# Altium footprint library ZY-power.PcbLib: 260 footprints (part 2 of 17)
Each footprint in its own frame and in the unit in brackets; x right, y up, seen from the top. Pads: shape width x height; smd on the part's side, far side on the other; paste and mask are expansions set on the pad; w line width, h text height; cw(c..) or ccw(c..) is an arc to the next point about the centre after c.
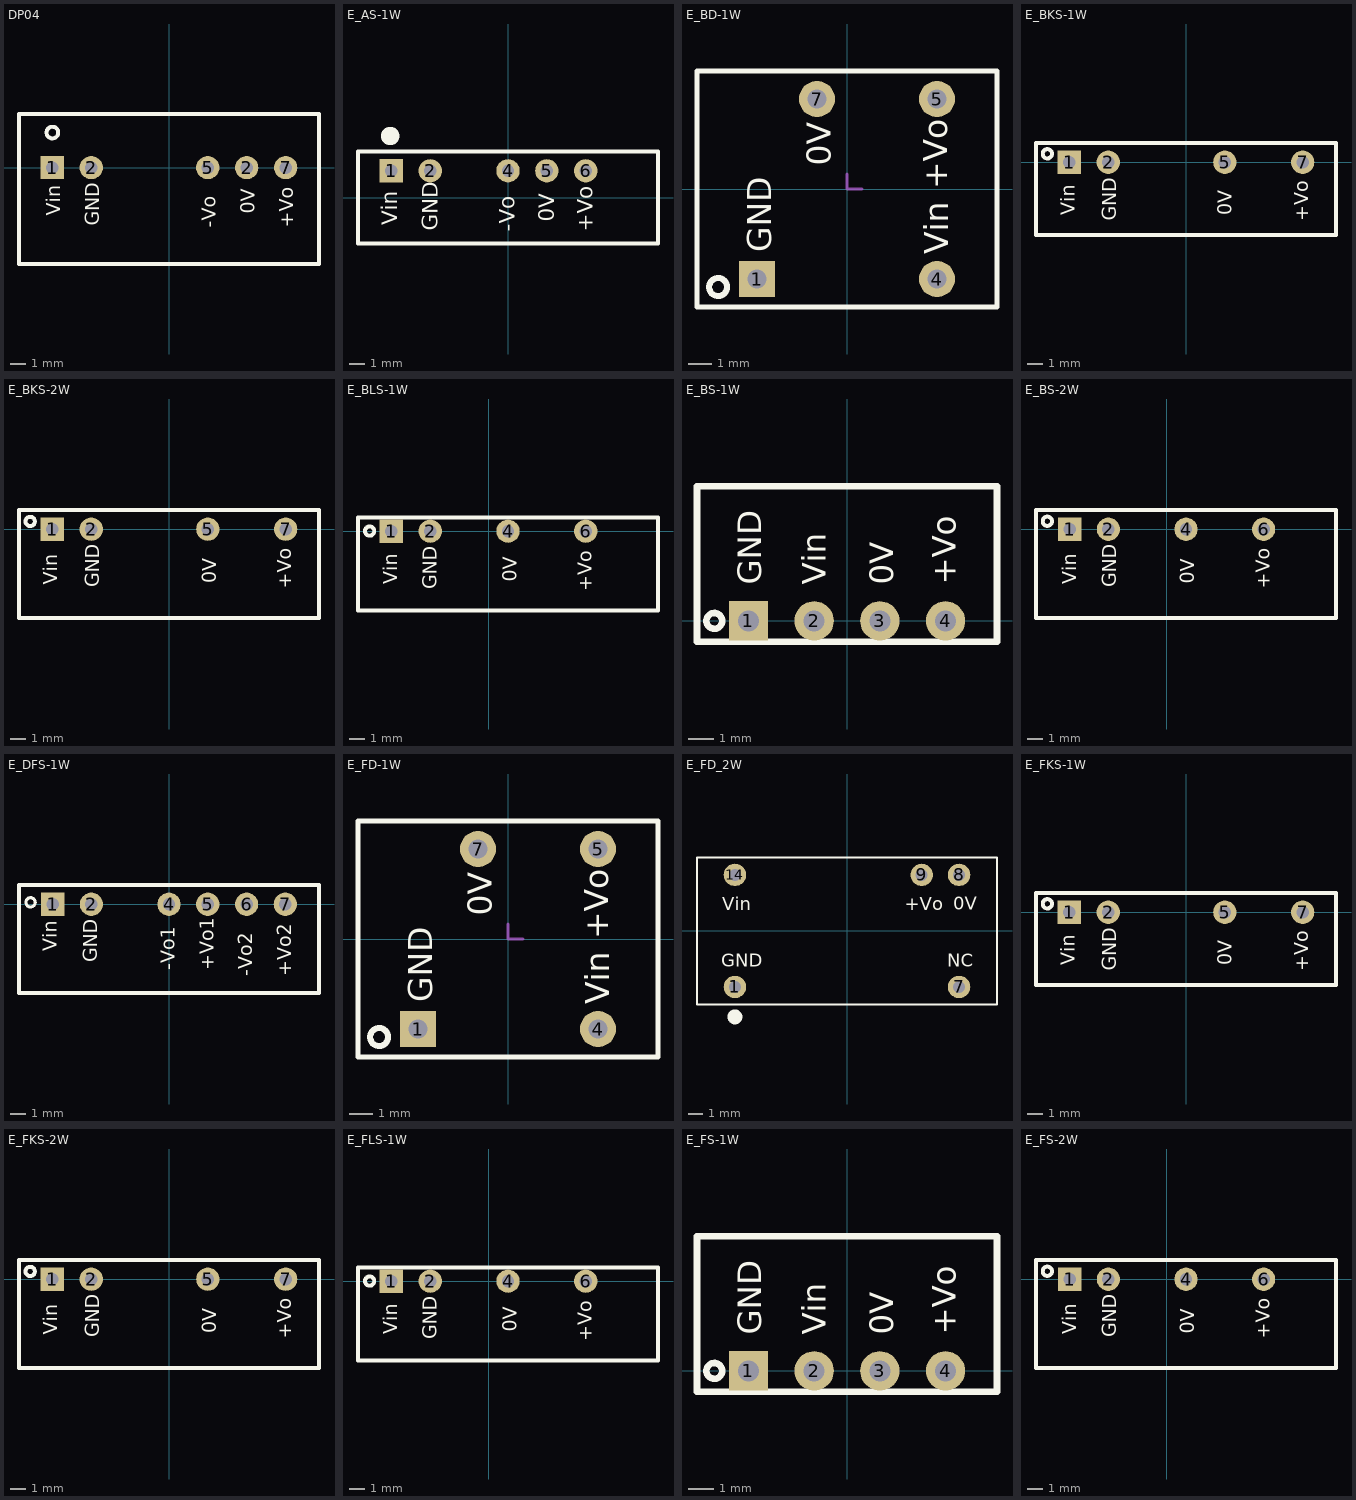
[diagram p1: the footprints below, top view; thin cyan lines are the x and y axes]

## DP04 [mil]
height 492.13
pads (5):
  rect 60x60 hole 32: 1(-300,0)
  round 60 hole 32: 2(-200,0) 2(199.74,0) 5(99.74,0) 7(300,0)
Top Overlay:
  circle w10: c-300,90 r15
  lines w10: -385.83,-248.03 -385.83,137.8 385.83,137.8 385.83,-248.03 -385.83,-248.03
  text "Vin" at -280,-123.29 h36
  text "GND" at -180,-150 h36
  text "-Vo" at 120,-155 h36
  text "+Vo" at 320,-155 h36
  text "0V" at 220,-118.67 h36

## E_AS-1W [mil]
height 393.7
pads (5):
  rect 60x60 hole 32: 1(-300,68.9)
  round 60 hole 32: 2(-200,68.9) 4(0,68.9) 5(100,68.9) 6(200,68.9)
Top Overlay:
  circle w39.37: c-303.15,158.46 r3.94
  lines w10: -385.83,-118.11 -385.83,118.11 385.83,118.11 385.83,-118.11 -385.83,-118.11
  text "Vin" at -284.45,-70.87 h40
  text "GND" at -180.12,-84.65 h40
  text "-Vo" at 17.72,-87.6 h40
  text "0V" at 118.6,-61.99 h40
  text "+Vo" at 218.5,-87.6 h40

## E_BD-1W [mil]
height 303.15
pads (4):
  rect 60x60 hole 32: 1(-150,-150)
  round 60 hole 32: 4(150,-150) 5(150,150) 7(-50,150)
Top Overlay:
  circle w10: c-214.8,-163.39 r15
  lines w8: -250,-196.85 250,-196.85 250,196.85 -250,196.85 -250,-196.85
  text "GND" at -126,-105 h40
  text "Vin" at 169,-109 h40
  text "+Vo" at 167.1,0 h40
  text "0V" at -27,39 h40
Mechanical 15:
  lines w5: 0,25 0,0 25,0

## E_BKS-1W [mil]
height 393.7
pads (4):
  rect 60x60 hole 32: 1(-300,0)
  round 60 hole 32: 2(-200,0) 5(100,0) 7(300,0)
Top Overlay:
  circle w10: c-356.49,21.65 r12
  lines w10: -385.83,-187.01 -385.83,49.21 385.83,49.21 385.83,-187.01 -385.83,-187.01
  text "+Vo" at 314.96,-151.57 h36
  text "0V" at 118.11,-135.83 h36
  text "GND" at -180,-150 h36
  text "Vin" at -286.42,-136.81 h36

## E_BKS-2W [mil]
height 393.7
pads (4):
  rect 60x60 hole 32: 1(-300,0)
  round 60 hole 32: 2(-200,0) 5(100,0) 7(300,0)
Top Overlay:
  circle w10: c-357,20 r12
  lines w10: -385.83,-228.35 -385.83,49.21 385.83,49.21 385.83,-228.35 -385.83,-228.35
  text "+Vo" at 315,-153 h36
  text "0V" at 121,-139 h36
  text "GND" at -180,-150 h36
  text "Vin" at -287,-143 h36

## E_BLS-1W [mil]
height 393.7
pads (4):
  rect 60x60 hole 32: 1(-250,0)
  round 60 hole 32: 2(-150,0) 4(50,0) 6(250,0)
Top Overlay:
  circle w10: c-306,0 r12
  lines w10: -335.83,-204.72 -335.83,35.43 435.83,35.43 435.83,-204.72 -335.83,-204.72
  text "+Vo" at 266,-155 h36
  text "0V" at 73,-130 h36
  text "GND" at -133,-150 h36
  text "Vin" at -235,-137 h36

## E_BS-1W [mil]
height 397.64
pads (4):
  rect 60x60 hole 32: 1(-150,0)
  round 60 hole 32: 2(-50,0) 3(50,0) 4(150,0)
Top Overlay:
  circle w10: c-202,0 r12
  lines w10: -228.35,-31.5 228.35,-31.5 228.35,204.72 -228.35,204.72 -228.35,-31.5
  text "GND" at -130.5,55 h36
  text "Vin" at -32.5,55 h36
  text "0V" at 70.5,55 h36
  text "+Vo" at 165.5,55 h36

## E_BS-2W [mil]
height 397.64
pads (4):
  rect 60x60 hole 32: 1(-250,0)
  round 60 hole 32: 2(-150,0) 4(50,0) 6(250,0)
Top Overlay:
  circle w10: c-307.47,20.67 r12
  lines w10: -336.81,-228.35 436.81,-228.35 436.81,49.21 -336.81,49.21 -336.81,-228.35
  text "Vin" at -233.46,-141.73 h36
  text "GND" at -130,-150 h36
  text "0V" at 70.67,-140.75 h36
  text "+Vo" at 265.55,-153.54 h36

## E_DFS-1W [mil]
height 397.64
pads (6):
  rect 60x60 hole 32: 1(-300,0)
  round 60 hole 32: 2(-200,0) 4(0,0) 5(100,0) 6(200,0) 7(300,0)
Top Overlay:
  circle w8: c-357,5 r12
  lines w10: -386.81,-228.35 -386.81,49.21 386.81,49.21 386.81,-228.35 -386.81,-228.35
  text "-Vo1" at 15,-169.57 h36
  text "Vin" at -290,-121.41 h36
  text "GND" at -185,-149.18 h36
  text "+Vo1" at 115,-169.57 h36
  text "-Vo2" at 215,-185 h36
  text "+Vo2" at 315,-185 h36

## E_FD-1W [mil]
height 303.15
pads (4):
  rect 60x60 hole 32: 1(-150,-150)
  round 60 hole 32: 4(150,-150) 5(150,150) 7(-50,150)
Top Overlay:
  circle w10: c-214.8,-163.39 r15
  lines w8: -250,-196.85 -250,196.85 250,196.85 250,-196.85 -250,-196.85
  text "0V" at -27,39 h40
  text "+Vo" at 167.1,0 h40
  text "Vin" at 169,-109 h40
  text "GND" at -126,-105 h40
Mechanical 15:
  lines w5: 0,25 0,0 25,0

## E_FD_2W [mil]
height 318.9
pads (5):
  round 60 hole 32 paste-31: 1(-300,-150) 7(300,-150) 8(300,150) 9(200,150) 14(-300,150)
Top Overlay:
  circle w20: c-300,-230 r10
  lines w5: -401.57,-196.85 401.57,-196.85 401.57,196.85 -401.57,196.85 -401.57,-196.85
  text "GND" at -337,-96 h35
  text "Vin" at -334,55 h35
  text "+Vo" at 154,56 h35
  text "0V" at 285,57 h35
  text "NC" at 268,-96 h35

## E_FKS-1W [mil]
height 393.7
pads (4):
  rect 60x60 hole 32: 1(-300,0)
  round 60 hole 32: 2(-200,0) 5(100,0) 7(300,0)
Top Overlay:
  circle w10: c-356.49,21.65 r12
  lines w10: -385.83,-187.01 385.83,-187.01 385.83,49.21 -385.83,49.21 -385.83,-187.01
  text "Vin" at -286.42,-136.81 h36
  text "GND" at -180,-150 h36
  text "0V" at 118.11,-135.83 h36
  text "+Vo" at 314.96,-151.57 h36

## E_FKS-2W [mil]
height 393.7
pads (4):
  rect 60x60 hole 32: 1(-300,0)
  round 60 hole 32: 2(-200,0) 5(100,0) 7(300,0)
Top Overlay:
  circle w10: c-357,20 r12
  lines w10: -385.83,-228.35 -385.83,49.21 385.83,49.21 385.83,-228.35 -385.83,-228.35
  text "+Vo" at 315,-153 h36
  text "0V" at 121,-139 h36
  text "GND" at -180,-150 h36
  text "Vin" at -287,-143 h36

## E_FLS-1W [mil]
height 393.7
pads (4):
  rect 60x60 hole 32: 1(-250,0)
  round 60 hole 32: 2(-150,0) 4(50,0) 6(250,0)
Top Overlay:
  circle w10: c-306,0 r12
  lines w10: -335.83,-204.72 -335.83,35.43 435.83,35.43 435.83,-204.72 -335.83,-204.72
  text "+Vo" at 266,-155 h36
  text "0V" at 73,-130 h36
  text "GND" at -133,-150 h36
  text "Vin" at -235,-137 h36

## E_FS-1W [mil]
height 397.64
pads (4):
  rect 60x60 hole 32: 1(-150,0)
  round 60 hole 32: 2(-50,0) 3(50,0) 4(150,0)
Top Overlay:
  circle w10: c-202,0 r12
  lines w10: -228.35,-31.5 228.35,-31.5 228.35,204.72 -228.35,204.72 -228.35,-31.5
  text "GND" at -130.5,55 h36
  text "Vin" at -32.5,55 h36
  text "0V" at 70.5,55 h36
  text "+Vo" at 165.5,55 h36

## E_FS-2W [mil]
height 397.64
pads (4):
  rect 60x60 hole 32: 1(-250,0)
  round 60 hole 32: 2(-150,0) 4(50,0) 6(250,0)
Top Overlay:
  circle w10: c-307.47,20.67 r12
  lines w10: -336.81,-228.35 -336.81,49.21 436.81,49.21 436.81,-228.35 -336.81,-228.35
  text "+Vo" at 265.55,-153.54 h36
  text "0V" at 70.67,-140.75 h36
  text "GND" at -130,-150 h36
  text "Vin" at -233.46,-141.73 h36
